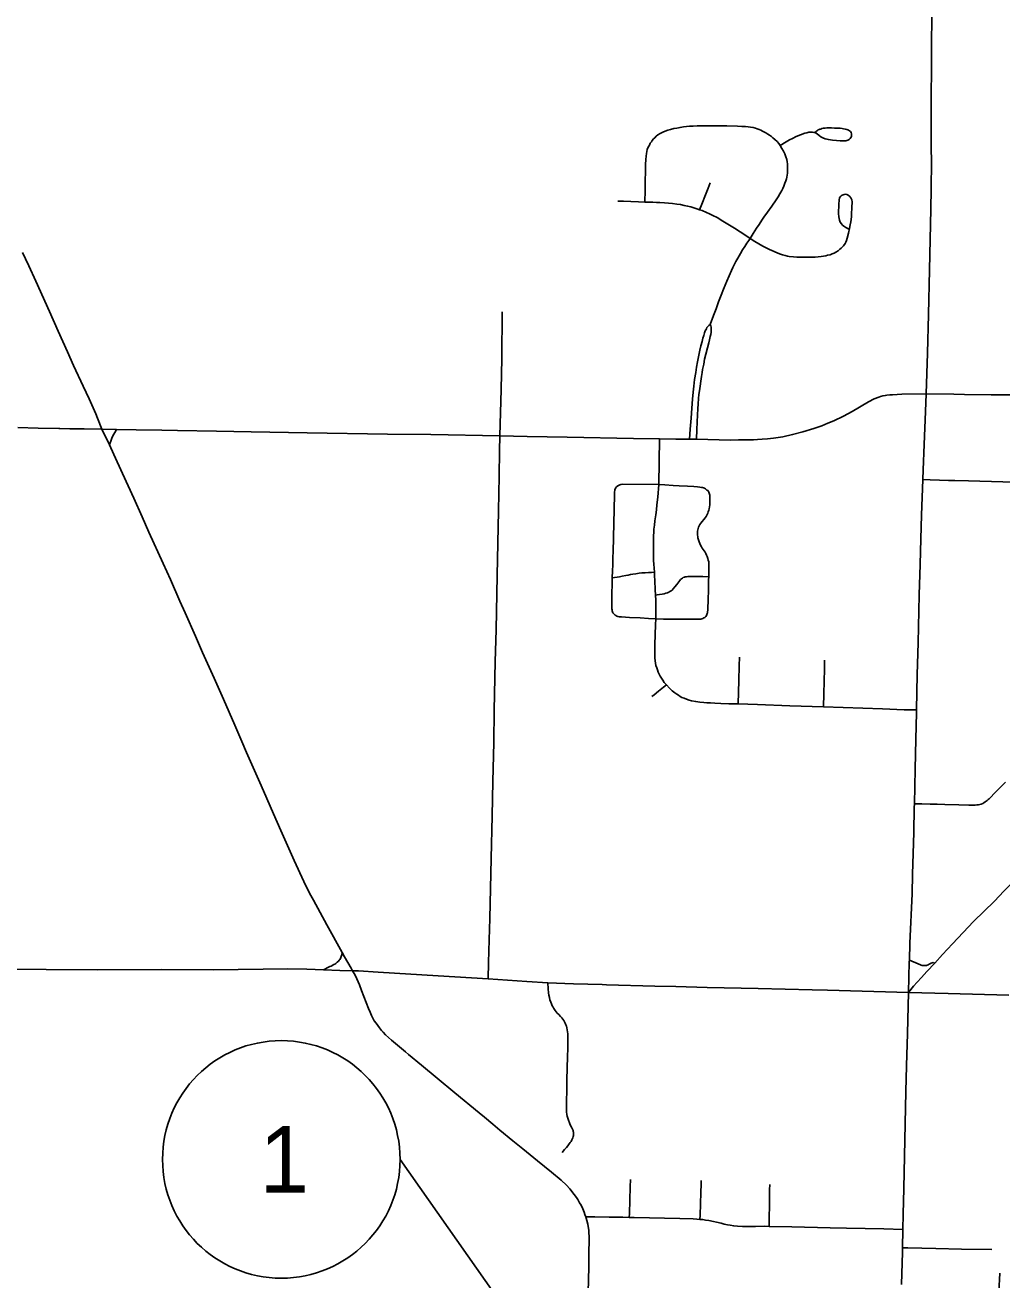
# Model space of a CAD drawing. Extents: x 1341221 to 1914484, y 79347 to 658398.
# Drawn here: x 1378615 to 1387868, y 622283 to 634169 of the extents above; entities that cross this region are included whole.
import ezdxf

# ---------------------------------------------------------------- set-up
doc = ezdxf.new("R2010")
doc.units = 0
for name, color, linetype in [('GM_X_County', 7, 'Continuous'), ('GM_X_State_Shield', 7, 'Continuous'), ('GM_X_Unincorporated', 7, 'Continuous'), ('GM_X_US_Shield', 7, 'Continuous')]:
    doc.layers.add(name, color=color, linetype=linetype)

msp = doc.modelspace()

# ---------------------------------------------------------------- linework, layer by layer
at = {"layer": 'GM_X_County'}
msp.add_line((1382167, 623424), (1387231, 616228), dxfattribs=at)
msp.add_circle((1381042, 623424), 1125, dxfattribs=at)
at = {"layer": 'GM_X_State_Shield'}
for points in [[(1384485, 632493), (1384487, 632604), (1384489, 632693), (1384491, 632781), (1384492, 632847), (1384494, 632897), (1384497, 632926), (1384500, 632953), (1384504, 632970), (1384509, 632989), (1384518, 633012), (1384528, 633032), (1384537, 633049), (1384547, 633064), (1384556, 633077), (1384566, 633090), (1384579, 633102), (1384593, 633116), (1384608, 633128), (1384629, 633143), (1384656, 633155), (1384679, 633165), (1384704, 633173), (1384730, 633181), (1384759, 633188), (1384789, 633194), (1384819, 633200), (1384853, 633205), (1384908, 633210), (1384942, 633212), (1384982, 633215), (1385031, 633216), (1385089, 633216), (1385172, 633216), (1385262, 633215), (1385363, 633212), (1385403, 633209), (1385439, 633207), (1385464, 633205), (1385487, 633202), (1385511, 633198), (1385533, 633191), (1385549, 633186), (1385567, 633179), (1385583, 633173), (1385601, 633163), (1385632, 633148), (1385651, 633136), (1385667, 633125), (1385685, 633112), (1385699, 633102), (1385718, 633086), (1385738, 633066), (1385754, 633046), (1385767, 633027)], [(1385767, 633027), (1385823, 633062), (1385855, 633081), (1385884, 633096), (1385918, 633113), (1385959, 633130), (1386002, 633145), (1386019, 633149), (1386039, 633153), (1386052, 633155), (1386065, 633155), (1386074, 633154), (1386085, 633152), (1386093, 633150), (1386102, 633147), (1386118, 633138), (1386137, 633122), (1386153, 633110), (1386170, 633100), (1386194, 633091), (1386211, 633087), (1386225, 633084), (1386263, 633079), (1386301, 633076), (1386336, 633073), (1386365, 633073), (1386390, 633074), (1386409, 633079), (1386420, 633085), (1386429, 633093), (1386437, 633104), (1386442, 633115), (1386444, 633128), (1386444, 633140), (1386439, 633152), (1386432, 633162), (1386425, 633168), (1386416, 633174), (1386407, 633178), (1386399, 633181), (1386384, 633184), (1386367, 633187), (1386353, 633189), (1386336, 633191), (1386321, 633192), (1386304, 633193), (1386281, 633194), (1386253, 633195), (1386240, 633195), (1386222, 633195), (1386208, 633195), (1386192, 633194), (1386176, 633192), (1386163, 633188), (1386151, 633184), (1386143, 633182), (1386136, 633179), (1386128, 633176), (1386120, 633171), (1386113, 633166), (1386107, 633162), (1386096, 633152)], [(1385104, 631334), (1385136, 631418), (1385160, 631481), (1385184, 631548), (1385209, 631611), (1385231, 631667), (1385263, 631744), (1385284, 631795), (1385305, 631843), (1385320, 631874), (1385332, 631898), (1385348, 631929), (1385366, 631961), (1385390, 632004), (1385411, 632039), (1385431, 632072), (1385451, 632102), (1385469, 632128), (1385482, 632148), (1385512, 632195), (1385544, 632245), (1385567, 632281), (1385593, 632320), (1385614, 632350), (1385648, 632396), (1385689, 632454), (1385730, 632513), (1385749, 632542), (1385765, 632569), (1385783, 632601), (1385794, 632622), (1385803, 632644), (1385812, 632670), (1385821, 632694), (1385826, 632712), (1385830, 632729), (1385833, 632747), (1385836, 632765), (1385838, 632786), (1385838, 632802), (1385838, 632814), (1385837, 632839), (1385836, 632856), (1385834, 632874), (1385829, 632897), (1385822, 632921), (1385811, 632948), (1385805, 632962), (1385798, 632976), (1385784, 633000), (1385767, 633027)], [(1385004, 632419), (1385025, 632471), (1385060, 632562), (1385084, 632623), (1385105, 632675)], [(1384229, 632502), (1384282, 632500), (1384354, 632497), (1384424, 632495), (1384485, 632493), (1384560, 632491), (1384595, 632489), (1384628, 632487), (1384671, 632484), (1384709, 632481), (1384746, 632478), (1384787, 632473), (1384822, 632468), (1384859, 632461), (1384890, 632454), (1384921, 632446), (1384950, 632438), (1384978, 632429), (1385004, 632419), (1385029, 632411), (1385069, 632395), (1385099, 632381), (1385130, 632366), (1385171, 632345), (1385225, 632313), (1385334, 632246), (1385441, 632175), (1385482, 632148), (1385526, 632119), (1385603, 632074), (1385666, 632042), (1385761, 632002), (1385789, 631992), (1385816, 631985), (1385836, 631980), (1385853, 631977), (1385892, 631974), (1385925, 631972), (1385965, 631971), (1386018, 631971), (1386070, 631972), (1386100, 631972), (1386128, 631974), (1386155, 631976), (1386179, 631980), (1386199, 631983), (1386217, 631988), (1386241, 631994), (1386259, 632001), (1386279, 632009), (1386294, 632017), (1386316, 632031), (1386333, 632045), (1386345, 632056), (1386358, 632069), (1386368, 632079), (1386383, 632099), (1386390, 632112), (1386396, 632129), (1386402, 632151), (1386413, 632197), (1386424, 632243), (1386431, 632278), (1386436, 632304), (1386439, 632328), (1386442, 632356), (1386444, 632379), (1386446, 632441), (1386448, 632494), (1386445, 632513), (1386437, 632531), (1386426, 632546), (1386411, 632558), (1386399, 632563), (1386386, 632566), (1386374, 632565), (1386356, 632558), (1386345, 632551), (1386336, 632542), (1386330, 632531), (1386326, 632512), (1386323, 632474), (1386320, 632383), (1386322, 632351), (1386329, 632320), (1386336, 632303), (1386347, 632287), (1386358, 632275), (1386370, 632265), (1386388, 632253), (1386403, 632244), (1386419, 632237)], [(1383111, 630277), (1383125, 630718), (1383130, 631012), (1383135, 631452)], [(1384908, 630246), (1384915, 630340), (1384923, 630447), (1384930, 630539), (1384937, 630624), (1384943, 630692), (1384949, 630748), (1384957, 630812), (1384967, 630877), (1384976, 630929), (1384985, 630978), (1385007, 631089), (1385017, 631130), (1385028, 631173), (1385036, 631202), (1385044, 631230), (1385052, 631253), (1385058, 631273), (1385068, 631292), (1385074, 631304), (1385082, 631314), (1385090, 631323), (1385104, 631334)], [(1384976, 630245), (1384979, 630337), (1384983, 630478), (1384986, 630535), (1384990, 630580), (1384994, 630631), (1384998, 630669), (1385002, 630704), (1385008, 630748), (1385015, 630797), (1385022, 630840), (1385028, 630877), (1385033, 630907), (1385043, 630956), (1385052, 631003), (1385064, 631053), (1385079, 631111), (1385090, 631159), (1385098, 631187), (1385105, 631218), (1385110, 631239), (1385114, 631261), (1385115, 631278), (1385115, 631292), (1385113, 631306), (1385110, 631319), (1385104, 631334)], [(1387059, 627683), (1386979, 627684), (1386941, 627684), (1386736, 627691), (1386179, 627710), (1385858, 627721), (1385553, 627732), (1385368, 627738), (1385281, 627741), (1385204, 627744), (1385148, 627746), (1385108, 627748), (1385074, 627749), (1385045, 627751), (1385005, 627755), (1384967, 627760), (1384928, 627768), (1384905, 627774), (1384879, 627783), (1384858, 627792), (1384837, 627801), (1384820, 627810), (1384804, 627820), (1384787, 627831), (1384768, 627845), (1384745, 627864), (1384720, 627887), (1384691, 627918), (1384670, 627942), (1384655, 627963), (1384642, 627982), (1384632, 628000), (1384621, 628020), (1384613, 628039), (1384604, 628061), (1384598, 628080), (1384591, 628104), (1384587, 628124), (1384583, 628148), (1384581, 628175), (1384580, 628197), (1384579, 628228), (1384579, 628263), (1384581, 628302), (1384587, 628489), (1384590, 628544), (1384590, 628575), (1384590, 628604), (1384590, 628640), (1384589, 628681), (1384588, 628722), (1384586, 628768), (1384583, 628823), (1384579, 628904), (1384577, 628954), (1384576, 628987), (1384573, 629026), (1384572, 629063), (1384569, 629097), (1384569, 629134), (1384567, 629164), (1384567, 629198), (1384566, 629252), (1384566, 629280), (1384567, 629305), (1384568, 629335), (1384570, 629362), (1384572, 629395), (1384576, 629431), (1384581, 629472), (1384589, 629530), (1384595, 629578), (1384600, 629625), (1384608, 629697), (1384617, 629818), (1384625, 630250)], [(1387119, 629864), (1387189, 629862), (1387275, 629859), (1387362, 629856), (1387423, 629854), (1387552, 629851), (1387877, 629842), (1387965, 629840), (1388165, 629834), (1388733, 629817), (1388915, 629812), (1388977, 629810), (1389079, 629808), (1389136, 629806), (1389328, 629802)], [(1384590, 628544), (1384519, 628549), (1384442, 628553), (1384341, 628558), (1384265, 628562), (1384253, 628563), (1384242, 628564), (1384230, 628567), (1384221, 628571), (1384212, 628575), (1384204, 628580), (1384195, 628588), (1384188, 628596), (1384183, 628603), (1384179, 628612), (1384176, 628621), (1384175, 628630), (1384174, 628640), (1384173, 628666), (1384173, 628687), (1384174, 628745), (1384174, 628806), (1384175, 628852), (1384176, 628891), (1384177, 628932), (1384179, 628998), (1384181, 629056), (1384183, 629128), (1384184, 629179), (1384198, 629719), (1384199, 629741), (1384201, 629766), (1384207, 629783), (1384217, 629796), (1384229, 629806), (1384247, 629813), (1384259, 629817), (1384277, 629819), (1384617, 629818)], [(1384590, 628544), (1384662, 628543), (1384802, 628542), (1384901, 628541), (1384981, 628540), (1385001, 628541), (1385017, 628543), (1385035, 628548), (1385045, 628553), (1385053, 628557), (1385062, 628566), (1385070, 628576), (1385074, 628586), (1385076, 628594), (1385078, 628602), (1385079, 628611), (1385081, 628627), (1385083, 628647), (1385083, 628667), (1385084, 628695), (1385086, 628750), (1385087, 628795), (1385088, 628838), (1385089, 628874), (1385089, 628913), (1385090, 628944), (1385091, 628973), (1385092, 628997), (1385093, 629027), (1385093, 629054), (1385090, 629086), (1385086, 629101), (1385082, 629117), (1385077, 629134), (1385071, 629147), (1385063, 629162), (1385056, 629175), (1385038, 629201), (1385029, 629215), (1385021, 629228), (1385012, 629244), (1385006, 629257), (1384999, 629274), (1384993, 629293), (1384988, 629311), (1384986, 629324), (1384984, 629338), (1384983, 629349), (1384983, 629362), (1384984, 629375), (1384986, 629388), (1384989, 629400), (1384994, 629413), (1384999, 629424), (1385007, 629438), (1385016, 629451), (1385056, 629501), (1385065, 629514), (1385073, 629528), (1385081, 629544), (1385085, 629557), (1385090, 629573), (1385094, 629588), (1385097, 629605), (1385100, 629626), (1385102, 629647), (1385102, 629671), (1385102, 629694), (1385100, 629715), (1385098, 629725), (1385096, 629734), (1385092, 629743), (1385087, 629751), (1385081, 629759), (1385074, 629765), (1385067, 629771), (1385059, 629777), (1385050, 629782), (1385042, 629785), (1385033, 629788), (1385023, 629790), (1385005, 629793), (1384985, 629794), (1384948, 629797), (1384890, 629800), (1384811, 629805), (1384753, 629809), (1384675, 629814), (1384617, 629818)], [(1384177, 628932), (1384245, 628944), (1384271, 628949), (1384305, 628955), (1384326, 628959), (1384349, 628963), (1384373, 628968), (1384401, 628972), (1384431, 628976), (1384458, 628979), (1384489, 628981), (1384520, 628984), (1384548, 628985), (1384576, 628987)], [(1384586, 628768), (1384602, 628771), (1384623, 628775), (1384648, 628779), (1384668, 628783), (1384685, 628787), (1384699, 628791), (1384712, 628797), (1384723, 628802), (1384734, 628809), (1384743, 628817), (1384755, 628828), (1384771, 628847), (1384789, 628870), (1384806, 628894), (1384816, 628907), (1384824, 628916), (1384834, 628925), (1384842, 628931), (1384850, 628935), (1384860, 628939), (1384868, 628941), (1384880, 628943), (1384894, 628945), (1384908, 628946), (1384923, 628946), (1384952, 628947), (1384991, 628946), (1385035, 628946), (1385090, 628944)], [(1385368, 627738), (1385375, 627960), (1385380, 628099), (1385383, 628182)], [(1386179, 627710), (1386182, 627833), (1386184, 627955), (1386186, 628069), (1386188, 628153)], [(1384551, 627808), (1384574, 627826), (1384616, 627859), (1384663, 627896), (1384691, 627918)], [(1387039, 626792), (1387109, 626791), (1387189, 626790), (1387255, 626788), (1387327, 626786), (1387458, 626783), (1387555, 626781), (1387613, 626780), (1387631, 626782), (1387646, 626784), (1387659, 626786), (1387672, 626790), (1387686, 626796), (1387697, 626802), (1387710, 626810), (1387719, 626817), (1387728, 626825), (1387737, 626833), (1387746, 626841), (1387753, 626847), (1387805, 626900), (1387863, 626958), (1387901, 626996)], [(1383702, 623488), (1383725, 623517), (1383743, 623537), (1383755, 623552), (1383763, 623562), (1383770, 623572), (1383779, 623584), (1383786, 623595), (1383793, 623608), (1383799, 623621), (1383803, 623630), (1383806, 623640), (1383809, 623649), (1383810, 623658), (1383811, 623665), (1383811, 623673), (1383810, 623681), (1383808, 623689), (1383805, 623699), (1383799, 623712), (1383790, 623731), (1383779, 623753), (1383771, 623772), (1383762, 623795), (1383756, 623814), (1383750, 623834), (1383747, 623851), (1383744, 623875), (1383743, 623896), (1383743, 623932), (1383743, 623972), (1383745, 624079), (1383747, 624177), (1383753, 624398), (1383755, 624476), (1383756, 624529), (1383757, 624556), (1383757, 624581), (1383757, 624596), (1383756, 624612), (1383754, 624631), (1383751, 624652), (1383748, 624669), (1383743, 624685), (1383738, 624699), (1383731, 624715), (1383725, 624728), (1383718, 624740), (1383710, 624751), (1383700, 624764), (1383688, 624778), (1383670, 624796), (1383656, 624810), (1383647, 624821), (1383635, 624834), (1383624, 624852), (1383616, 624865), (1383608, 624879), (1383600, 624898), (1383594, 624915), (1383586, 624937), (1383581, 624958), (1383577, 624981), (1383574, 625002), (1383571, 625041), (1383567, 625096)], [(1384338, 622874), (1384339, 622912), (1384347, 623165), (1384350, 623233)], [(1385006, 622856), (1385008, 622897), (1385015, 623112), (1385019, 623189), (1385020, 623223)], [(1385664, 622790), (1385664, 622813), (1385665, 623047), (1385666, 623135), (1385668, 623187)], [(1383926, 622880), (1384013, 622881), (1384148, 622878), (1384276, 622876), (1384338, 622874), (1384385, 622873), (1384816, 622865), (1384944, 622860), (1384978, 622859), (1385006, 622856), (1385034, 622854), (1385061, 622849), (1385091, 622845), (1385209, 622819), (1385238, 622812), (1385269, 622805), (1385295, 622800), (1385327, 622794), (1385364, 622791), (1385410, 622789), (1385471, 622789), (1385534, 622790), (1385622, 622791), (1385664, 622790), (1385878, 622784), (1386241, 622775), (1386394, 622772), (1386749, 622765), (1386930, 622761)], [(1386926, 622587), (1386977, 622586), (1387241, 622581), (1387484, 622575), (1387771, 622570)], [(1387780, 622070), (1387792, 622071), (1387798, 622073), (1387805, 622076), (1387812, 622080), (1387816, 622083), (1387822, 622090), (1387827, 622097), (1387831, 622103), (1387834, 622110), (1387835, 622118), (1387836, 622127), (1387838, 622143), (1387839, 622169), (1387848, 622347)]]:
    msp.add_lwpolyline(points, dxfattribs=at)
at = {"layer": 'GM_X_Unincorporated'}
for p, q in [((1387198, 633314), (1387198, 633441)), ((1387198, 633171), (1387198, 633314)), ((1387198, 633089), (1387198, 633171))]:
    msp.add_line(p, q, dxfattribs=at)
for points in [[(1387198, 633441), (1387198, 633549), (1387200, 633701), (1387202, 633809), (1387202, 633952), (1387205, 634275), (1387205, 634395), (1387218, 634985), (1387224, 635259), (1387228, 635435), (1387228, 635465)], [(1387200, 632876), (1387200, 632886), (1387199, 632998), (1387198, 633089)], [(1386917, 622238), (1386925, 622545), (1386926, 622587), (1386930, 622761), (1386933, 622905), (1386938, 623148), (1386959, 624068), (1386964, 624311), (1386973, 624617), (1386983, 625004), (1386990, 625297), (1386991, 625312), (1386997, 625472), (1387016, 625939), (1387020, 626125), (1387026, 626323), (1387032, 626521), (1387038, 626758), (1387039, 626792), (1387046, 627121), (1387052, 627404), (1387058, 627654), (1387059, 627683), (1387066, 628018), (1387073, 628318), (1387080, 628619), (1387084, 628772), (1387093, 629060), (1387100, 629303), (1387107, 629527), (1387119, 629864), (1387122, 629955), (1387130, 630197), (1387143, 630508), (1387151, 630677), (1387163, 631060), (1387171, 631428), (1387181, 631850), (1387193, 632426), (1387198, 632618), (1387200, 632876)]]:
    msp.add_lwpolyline(points, dxfattribs=at)
at = {"layer": 'GM_X_US_Shield'}
for p, q in [((1379341, 630341), (1379301, 630444)), ((1379416, 630192), (1379341, 630341))]:
    msp.add_line(p, q, dxfattribs=at)
for points in [[(1379074, 630945), (1379018, 631073), (1378929, 631271), (1378845, 631457), (1378716, 631743), (1378650, 631888), (1378619, 631956), (1378591, 632016)], [(1379301, 630444), (1379284, 630488), (1379221, 630627), (1379165, 630749), (1379074, 630945)], [(1385463, 630239), (1385474, 630239), (1385514, 630240), (1385552, 630242), (1385597, 630245), (1385648, 630250), (1385704, 630257), (1385791, 630270), (1385885, 630290), (1385983, 630315), (1386086, 630347), (1386163, 630374), (1386220, 630397), (1386274, 630421), (1386366, 630465), (1386450, 630510), (1386604, 630601), (1386657, 630628), (1386701, 630645), (1386719, 630651), (1386739, 630656), (1386762, 630660), (1386779, 630663), (1386807, 630665), (1386832, 630667), (1386920, 630673), (1387151, 630677)], [(1389364, 630630), (1388929, 630639), (1388312, 630659), (1388018, 630666), (1387767, 630668), (1387514, 630670), (1387411, 630672), (1387151, 630677)], [(1378546, 630356), (1378739, 630350), (1378934, 630346), (1378944, 630346)], [(1378944, 630346), (1379038, 630345), (1379175, 630343), (1379341, 630341)], [(1379341, 630341), (1379480, 630339), (1379667, 630335), (1379911, 630332), (1380058, 630329), (1380429, 630322), (1380755, 630317), (1381286, 630308), (1382048, 630295), (1382457, 630291), (1383111, 630277), (1383372, 630272), (1383750, 630266), (1384377, 630254), (1384625, 630250), (1384780, 630247), (1384908, 630246), (1384946, 630245)], [(1379416, 630192), (1379431, 630236), (1379441, 630266), (1379456, 630294), (1379465, 630310), (1379480, 630339)], [(1383002, 625134), (1383006, 625290), (1383012, 625505), (1383018, 625705), (1383029, 626274), (1383038, 626680), (1383046, 627003), (1383054, 627374), (1383059, 627675), (1383069, 628142), (1383077, 628442), (1383087, 628954), (1383100, 629568), (1383105, 629897), (1383109, 630136), (1383111, 630277)], [(1384946, 630245), (1384976, 630245), (1385298, 630238), (1385374, 630239), (1385432, 630239), (1385463, 630239)], [(1381717, 625211), (1381703, 625235), (1381642, 625343), (1381620, 625383), (1381473, 625647), (1381346, 625879), (1381322, 625923), (1381301, 625966), (1381256, 626057), (1381165, 626255), (1381049, 626511), (1380991, 626646), (1380850, 626965), (1380712, 627278), (1380667, 627383), (1380602, 627536), (1380496, 627784), (1380407, 627982), (1380296, 628227), (1380229, 628379), (1380131, 628601), (1380082, 628713), (1379992, 628918), (1379923, 629069), (1379787, 629366), (1379723, 629512), (1379644, 629687), (1379539, 629921), (1379457, 630101), (1379416, 630192)], [(1386983, 625004), (1387031, 625065), (1387065, 625104), (1387106, 625148), (1387156, 625203), (1387231, 625282), (1387305, 625366), (1387399, 625465), (1387500, 625572), (1387600, 625678), (1387796, 625871), (1387887, 625965), (1388028, 626109), (1388215, 626302), (1388404, 626494), (1388539, 626630), (1388654, 626750), (1388769, 626865), (1388819, 626916), (1388841, 626938)], [(1381443, 625221), (1381489, 625244), (1381503, 625251), (1381514, 625256), (1381539, 625269), (1381549, 625275), (1381557, 625280), (1381565, 625286), (1381572, 625291), (1381584, 625303), (1381591, 625310), (1381597, 625318), (1381602, 625327), (1381606, 625337), (1381610, 625346), (1381615, 625363), (1381620, 625383)], [(1378516, 625226), (1378816, 625224)], [(1378816, 625224), (1379303, 625220), (1379903, 625222), (1380401, 625221), (1381104, 625229), (1381284, 625226), (1381443, 625221), (1381597, 625214), (1381717, 625211)], [(1383949, 622162), (1383954, 622408), (1383954, 622531), (1383957, 622673), (1383954, 622751), (1383945, 622810), (1383926, 622880), (1383918, 622902), (1383911, 622925), (1383897, 622956), (1383882, 622990), (1383868, 623014), (1383851, 623043), (1383839, 623064), (1383817, 623092), (1383776, 623145), (1383744, 623180), (1383694, 623227), (1383601, 623302), (1383468, 623410), (1383329, 623523), (1383235, 623599), (1383113, 623702), (1383046, 623758), (1382966, 623824), (1382915, 623864), (1382686, 624055), (1382517, 624193), (1382369, 624316), (1382246, 624418), (1382217, 624443), (1382085, 624554), (1382029, 624605), (1382007, 624628), (1381990, 624646), (1381972, 624669), (1381955, 624691), (1381939, 624714), (1381923, 624738), (1381910, 624763), (1381896, 624788), (1381883, 624818), (1381868, 624852), (1381801, 625025), (1381782, 625078), (1381757, 625133), (1381743, 625168), (1381717, 625211)], [(1381717, 625211), (1381772, 625209), (1381961, 625198), (1382528, 625164), (1383002, 625134), (1383367, 625109), (1383567, 625096), (1383811, 625088), (1384080, 625080), (1384122, 625079)], [(1386991, 625312), (1387074, 625277), (1387097, 625267), (1387104, 625264), (1387113, 625262), (1387129, 625260), (1387139, 625260), (1387152, 625262), (1387161, 625264), (1387169, 625267), (1387180, 625273), (1387190, 625279), (1387199, 625284), (1387208, 625287), (1387218, 625288), (1387231, 625282)], [(1384122, 625079), (1384579, 625066), (1384778, 625061), (1385077, 625052), (1385559, 625043), (1386070, 625030)], [(1386070, 625030), (1386216, 625026), (1386983, 625004)], [(1386983, 625004), (1387360, 624997), (1387932, 624981)]]:
    msp.add_lwpolyline(points, dxfattribs=at)

# ---------------------------------------------------------------- texts
at = {"layer": 'GM_X_County'}
msp.add_text('1', height=630, dxfattribs=at).set_placement((1380836, 623109))

doc.saveas('drawing.dxf')
